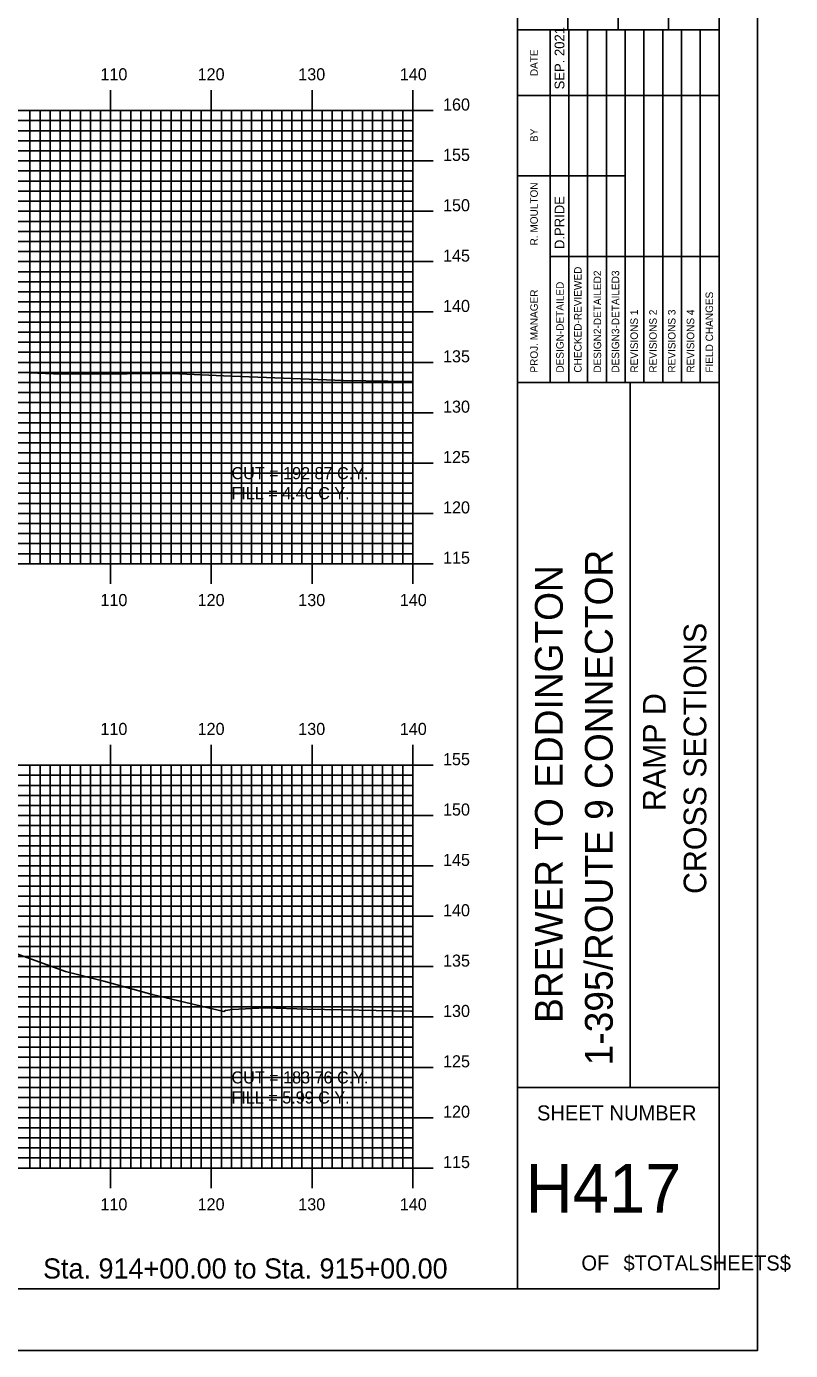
# Model space of a CAD drawing. Extents: x 860652 to 860995, y 364765 to 364985.
# Drawn here: x 860919.1 to 860994.9, y 364765.2 to 364896.6 of the extents above; entities that cross this region are included whole.
import ezdxf

# ---------------------------------------------------------------- set-up
doc = ezdxf.new("R2010")
doc.units = 0
for name, color, linetype in [('BORDER', 7, 'Continuous'), ('D_Text_Standard', 7, 'Continuous'), ('H_V ANNOTATION', 7, 'Continuous'), ('MAJOR', 7, 'Continuous'), ('MINOR', 7, 'Continuous'), ('PLOT BOUNDARY', 7, 'Continuous'), ('S_Roadway_Centerline', 7, 'Continuous')]:
    doc.layers.add(name, color=color, linetype=linetype)

msp = doc.modelspace()

# ---------------------------------------------------------------- linework, layer by layer
at = {"layer": 'BORDER'}
for p, q in [((860967.81, 364771.3), (860967.81, 364981.3)), ((860972.81, 364896.31), (860972.81, 364913.6)), ((860977.81, 364896.31), (860977.81, 364913.6)), ((860982.81, 364896.31), (860982.81, 364913.6)), ((860967.81, 364896.31), (860987.81, 364896.31)), ((860967.81, 364861.31), (860987.81, 364861.31)), ((860978.99, 364791.31), (860978.99, 364861.31)), ((860967.81, 364791.31), (860987.81, 364791.31))]:
    msp.add_line(p, q, dxfattribs=at)
msp.add_lwpolyline([(860667.81, 364771.3), (860987.81, 364771.3), (860987.81, 364981.3), (860667.81, 364981.3)], close=True, dxfattribs=at)
for points in [[(860971.04, 364889.81), (860971.04, 364896.31)], [(860972.91, 364861.31), (860972.91, 364896.31)], [(860974.77, 364896.31), (860974.77, 364861.31)], [(860976.63, 364861.31), (860976.63, 364896.31)], [(860978.5, 364861.31), (860978.5, 364896.31)], [(860980.36, 364861.31), (860980.36, 364896.31)], [(860982.22, 364861.31), (860982.22, 364896.31)], [(860984.09, 364861.31), (860984.09, 364896.31)], [(860985.95, 364861.31), (860985.95, 364896.31)], [(860971.04, 364861.31), (860971.04, 364894.9)], [(860967.81, 364889.81), (860987.81, 364889.81)], [(860967.81, 364881.81), (860971.04, 364881.81)], [(860971.04, 364881.81), (860978.5, 364881.81)], [(860971.04, 364873.81), (860987.81, 364873.81)]]:
    msp.add_lwpolyline(points, dxfattribs=at)
at = {"layer": 'MAJOR'}
for p, q in [((860927.41, 364890.31), (860927.41, 364888.3)), ((860937.41, 364890.31), (860937.41, 364888.3)), ((860947.41, 364890.31), (860947.41, 364888.3)), ((860957.41, 364890.31), (860957.41, 364888.3)), ((860677.41, 364888.3), (860957.41, 364888.3)), ((860677.41, 364888.3), (860957.41, 364888.3)), ((860927.41, 364843.3), (860927.41, 364888.3)), ((860937.41, 364843.3), (860937.41, 364888.3)), ((860947.41, 364843.3), (860947.41, 364888.3)), ((860959.42, 364888.3), (860955.41, 364888.3)), ((860957.41, 364843.3), (860957.41, 364888.3)), ((860957.41, 364843.3), (860957.41, 364888.3)), ((860677.41, 364883.3), (860957.41, 364883.3)), ((860959.42, 364883.3), (860955.41, 364883.3)), ((860677.41, 364878.3), (860957.41, 364878.3)), ((860959.42, 364878.3), (860955.41, 364878.3)), ((860677.41, 364873.3), (860957.41, 364873.3)), ((860959.42, 364873.3), (860955.41, 364873.3)), ((860677.41, 364868.3), (860957.41, 364868.3)), ((860959.42, 364868.3), (860955.41, 364868.3)), ((860677.41, 364863.3), (860957.41, 364863.3)), ((860959.42, 364863.3), (860955.41, 364863.3)), ((860677.41, 364858.3), (860957.41, 364858.3)), ((860959.42, 364858.3), (860955.41, 364858.3)), ((860677.41, 364853.3), (860957.41, 364853.3)), ((860959.42, 364853.3), (860955.41, 364853.3)), ((860677.41, 364848.3), (860957.41, 364848.3)), ((860959.42, 364848.3), (860955.41, 364848.3)), ((860677.41, 364843.3), (860957.41, 364843.3)), ((860677.41, 364843.3), (860957.41, 364843.3)), ((860927.41, 364841.3), (860927.41, 364843.3)), ((860937.41, 364841.3), (860937.41, 364843.3)), ((860947.41, 364841.3), (860947.41, 364843.3)), ((860959.42, 364843.3), (860955.41, 364843.3)), ((860957.41, 364841.3), (860957.41, 364843.3)), ((860927.41, 364825.31), (860927.41, 364823.3)), ((860937.41, 364825.31), (860937.41, 364823.3)), ((860947.41, 364825.31), (860947.41, 364823.3)), ((860957.41, 364825.31), (860957.41, 364823.3)), ((860677.41, 364823.3), (860957.41, 364823.3)), ((860677.41, 364823.3), (860957.41, 364823.3)), ((860927.41, 364783.3), (860927.41, 364823.3)), ((860937.41, 364783.3), (860937.41, 364823.3)), ((860947.41, 364783.3), (860947.41, 364823.3)), ((860959.42, 364823.3), (860955.41, 364823.3)), ((860957.41, 364783.3), (860957.41, 364823.3)), ((860957.41, 364783.3), (860957.41, 364823.3)), ((860677.41, 364818.3), (860957.41, 364818.3)), ((860959.42, 364818.3), (860955.41, 364818.3)), ((860677.41, 364813.3), (860957.41, 364813.3)), ((860959.42, 364813.3), (860955.41, 364813.3)), ((860677.41, 364808.3), (860957.41, 364808.3)), ((860959.42, 364808.3), (860955.41, 364808.3)), ((860677.41, 364803.3), (860957.41, 364803.3)), ((860959.42, 364803.3), (860955.41, 364803.3)), ((860677.41, 364798.3), (860957.41, 364798.3)), ((860959.42, 364798.3), (860955.41, 364798.3)), ((860677.41, 364793.3), (860957.41, 364793.3)), ((860959.42, 364793.3), (860955.41, 364793.3)), ((860677.41, 364788.3), (860957.41, 364788.3)), ((860959.42, 364788.3), (860955.41, 364788.3)), ((860677.41, 364783.3), (860957.41, 364783.3)), ((860677.41, 364783.3), (860957.41, 364783.3)), ((860927.41, 364781.3), (860927.41, 364783.3)), ((860937.41, 364781.3), (860937.41, 364783.3)), ((860947.41, 364781.3), (860947.41, 364783.3)), ((860959.42, 364783.3), (860955.41, 364783.3)), ((860957.41, 364781.3), (860957.41, 364783.3))]:
    msp.add_line(p, q, dxfattribs=at)
at = {"layer": 'MINOR'}
for p, q in [((860919.41, 364843.3), (860919.41, 364888.3)), ((860920.41, 364843.3), (860920.41, 364888.3)), ((860921.41, 364843.3), (860921.41, 364888.3)), ((860922.41, 364843.3), (860922.41, 364888.3)), ((860923.41, 364843.3), (860923.41, 364888.3)), ((860924.41, 364843.3), (860924.41, 364888.3)), ((860925.41, 364843.3), (860925.41, 364888.3)), ((860926.41, 364843.3), (860926.41, 364888.3)), ((860928.41, 364843.3), (860928.41, 364888.3)), ((860929.41, 364843.3), (860929.41, 364888.3)), ((860930.41, 364843.3), (860930.41, 364888.3)), ((860931.41, 364843.3), (860931.41, 364888.3)), ((860932.41, 364843.3), (860932.41, 364888.3)), ((860933.41, 364843.3), (860933.41, 364888.3)), ((860934.41, 364843.3), (860934.41, 364888.3)), ((860935.41, 364843.3), (860935.41, 364888.3)), ((860936.41, 364843.3), (860936.41, 364888.3)), ((860938.41, 364843.3), (860938.41, 364888.3)), ((860939.41, 364843.3), (860939.41, 364888.3)), ((860940.41, 364843.3), (860940.41, 364888.3)), ((860941.41, 364843.3), (860941.41, 364888.3)), ((860942.41, 364843.3), (860942.41, 364888.3)), ((860943.41, 364843.3), (860943.41, 364888.3)), ((860944.41, 364843.3), (860944.41, 364888.3)), ((860945.41, 364843.3), (860945.41, 364888.3)), ((860946.41, 364843.3), (860946.41, 364888.3)), ((860948.41, 364843.3), (860948.41, 364888.3)), ((860949.41, 364843.3), (860949.41, 364888.3)), ((860950.41, 364843.3), (860950.41, 364888.3)), ((860951.41, 364843.3), (860951.41, 364888.3)), ((860952.41, 364843.3), (860952.41, 364888.3)), ((860953.41, 364843.3), (860953.41, 364888.3)), ((860954.41, 364843.3), (860954.41, 364888.3)), ((860955.41, 364843.3), (860955.41, 364888.3)), ((860956.41, 364843.3), (860956.41, 364888.3)), ((860677.41, 364887.3), (860957.41, 364887.3)), ((860957.41, 364887.3), (860955.41, 364887.3)), ((860677.41, 364886.3), (860957.41, 364886.3)), ((860677.41, 364885.3), (860957.41, 364885.3)), ((860957.41, 364886.3), (860955.41, 364886.3)), ((860957.41, 364885.3), (860955.41, 364885.3)), ((860677.41, 364884.3), (860957.41, 364884.3)), ((860957.41, 364884.3), (860955.41, 364884.3)), ((860677.41, 364882.3), (860957.41, 364882.3)), ((860957.41, 364882.3), (860955.41, 364882.3)), ((860677.41, 364881.3), (860957.41, 364881.3)), ((860677.41, 364880.3), (860957.41, 364880.3)), ((860957.41, 364881.3), (860955.41, 364881.3)), ((860957.41, 364880.3), (860955.41, 364880.3)), ((860677.41, 364879.3), (860957.41, 364879.3)), ((860957.41, 364879.3), (860955.41, 364879.3)), ((860677.41, 364877.3), (860957.41, 364877.3)), ((860677.41, 364876.3), (860957.41, 364876.3)), ((860957.41, 364877.3), (860955.41, 364877.3)), ((860957.41, 364876.3), (860955.41, 364876.3)), ((860677.41, 364875.3), (860957.41, 364875.3)), ((860957.41, 364875.3), (860955.41, 364875.3)), ((860677.41, 364874.3), (860957.41, 364874.3)), ((860957.41, 364874.3), (860955.41, 364874.3)), ((860677.41, 364872.3), (860957.41, 364872.3)), ((860957.41, 364872.3), (860955.41, 364872.3)), ((860677.41, 364871.3), (860957.41, 364871.3)), ((860957.41, 364871.3), (860955.41, 364871.3)), ((860677.41, 364870.3), (860957.41, 364870.3)), ((860957.41, 364870.3), (860955.41, 364870.3)), ((860677.41, 364869.3), (860957.41, 364869.3)), ((860957.41, 364869.3), (860955.41, 364869.3)), ((860677.41, 364867.3), (860957.41, 364867.3)), ((860957.41, 364867.3), (860955.41, 364867.3)), ((860677.41, 364866.3), (860957.41, 364866.3)), ((860957.41, 364866.3), (860955.41, 364866.3)), ((860677.41, 364865.3), (860957.41, 364865.3)), ((860677.41, 364864.3), (860957.41, 364864.3)), ((860957.41, 364865.3), (860955.41, 364865.3)), ((860957.41, 364864.3), (860955.41, 364864.3)), ((860677.41, 364862.3), (860957.41, 364862.3)), ((860957.41, 364862.3), (860955.41, 364862.3)), ((860677.41, 364861.3), (860957.41, 364861.3)), ((860677.41, 364860.3), (860957.41, 364860.3)), ((860957.41, 364861.3), (860955.41, 364861.3)), ((860957.41, 364860.3), (860955.41, 364860.3)), ((860677.41, 364859.3), (860957.41, 364859.3)), ((860957.41, 364859.3), (860955.41, 364859.3)), ((860677.41, 364857.3), (860957.41, 364857.3)), ((860957.41, 364857.3), (860955.41, 364857.3)), ((860677.41, 364856.3), (860957.41, 364856.3)), ((860677.41, 364855.3), (860957.41, 364855.3)), ((860957.41, 364856.3), (860955.41, 364856.3)), ((860957.41, 364855.3), (860955.41, 364855.3)), ((860677.41, 364854.3), (860957.41, 364854.3)), ((860957.41, 364854.3), (860955.41, 364854.3)), ((860677.41, 364852.3), (860957.41, 364852.3)), ((860677.41, 364851.3), (860957.41, 364851.3)), ((860957.41, 364852.3), (860955.41, 364852.3)), ((860957.41, 364851.3), (860955.41, 364851.3)), ((860677.41, 364850.3), (860957.41, 364850.3)), ((860957.41, 364850.3), (860955.41, 364850.3)), ((860677.41, 364849.3), (860957.41, 364849.3)), ((860957.41, 364849.3), (860955.41, 364849.3)), ((860677.41, 364847.3), (860957.41, 364847.3)), ((860957.41, 364847.3), (860955.41, 364847.3)), ((860677.41, 364846.3), (860957.41, 364846.3)), ((860957.41, 364846.3), (860955.41, 364846.3)), ((860677.41, 364845.3), (860957.41, 364845.3)), ((860957.41, 364845.3), (860955.41, 364845.3)), ((860677.41, 364844.3), (860957.41, 364844.3)), ((860957.41, 364844.3), (860955.41, 364844.3)), ((860677.41, 364822.3), (860957.41, 364822.3)), ((860919.41, 364783.3), (860919.41, 364823.3)), ((860920.41, 364783.3), (860920.41, 364823.3)), ((860921.41, 364783.3), (860921.41, 364823.3)), ((860922.41, 364783.3), (860922.41, 364823.3)), ((860923.41, 364783.3), (860923.41, 364823.3)), ((860924.41, 364783.3), (860924.41, 364823.3)), ((860925.41, 364783.3), (860925.41, 364823.3)), ((860926.41, 364783.3), (860926.41, 364823.3)), ((860928.41, 364783.3), (860928.41, 364823.3)), ((860929.41, 364783.3), (860929.41, 364823.3)), ((860930.41, 364783.3), (860930.41, 364823.3)), ((860931.41, 364783.3), (860931.41, 364823.3)), ((860932.41, 364783.3), (860932.41, 364823.3)), ((860933.41, 364783.3), (860933.41, 364823.3)), ((860934.41, 364783.3), (860934.41, 364823.3)), ((860935.41, 364783.3), (860935.41, 364823.3)), ((860936.41, 364783.3), (860936.41, 364823.3)), ((860938.41, 364783.3), (860938.41, 364823.3)), ((860939.41, 364783.3), (860939.41, 364823.3)), ((860940.41, 364783.3), (860940.41, 364823.3)), ((860941.41, 364783.3), (860941.41, 364823.3)), ((860942.41, 364783.3), (860942.41, 364823.3)), ((860943.41, 364783.3), (860943.41, 364823.3)), ((860944.41, 364783.3), (860944.41, 364823.3)), ((860945.41, 364783.3), (860945.41, 364823.3)), ((860946.41, 364783.3), (860946.41, 364823.3)), ((860948.41, 364783.3), (860948.41, 364823.3)), ((860949.41, 364783.3), (860949.41, 364823.3)), ((860950.41, 364783.3), (860950.41, 364823.3)), ((860951.41, 364783.3), (860951.41, 364823.3)), ((860952.41, 364783.3), (860952.41, 364823.3)), ((860953.41, 364783.3), (860953.41, 364823.3)), ((860954.41, 364783.3), (860954.41, 364823.3)), ((860955.41, 364783.3), (860955.41, 364823.3)), ((860957.41, 364822.3), (860955.41, 364822.3)), ((860956.41, 364783.3), (860956.41, 364823.3)), ((860677.41, 364821.3), (860957.41, 364821.3)), ((860957.41, 364821.3), (860955.41, 364821.3)), ((860677.41, 364820.3), (860957.41, 364820.3)), ((860957.41, 364820.3), (860955.41, 364820.3)), ((860677.41, 364819.3), (860957.41, 364819.3)), ((860957.41, 364819.3), (860955.41, 364819.3)), ((860677.41, 364817.3), (860957.41, 364817.3)), ((860957.41, 364817.3), (860955.41, 364817.3)), ((860677.41, 364816.3), (860957.41, 364816.3)), ((860957.41, 364816.3), (860955.41, 364816.3)), ((860677.41, 364815.3), (860957.41, 364815.3)), ((860677.41, 364814.3), (860957.41, 364814.3)), ((860957.41, 364815.3), (860955.41, 364815.3)), ((860957.41, 364814.3), (860955.41, 364814.3)), ((860677.41, 364812.3), (860957.41, 364812.3)), ((860957.41, 364812.3), (860955.41, 364812.3)), ((860677.41, 364811.3), (860957.41, 364811.3)), ((860957.41, 364811.3), (860955.41, 364811.3)), ((860677.41, 364810.3), (860957.41, 364810.3)), ((860677.41, 364809.3), (860957.41, 364809.3)), ((860957.41, 364810.3), (860955.41, 364810.3)), ((860957.41, 364809.3), (860955.41, 364809.3)), ((860677.41, 364807.3), (860957.41, 364807.3)), ((860957.41, 364807.3), (860955.41, 364807.3)), ((860677.41, 364806.3), (860957.41, 364806.3)), ((860677.41, 364805.3), (860957.41, 364805.3)), ((860957.41, 364806.3), (860955.41, 364806.3)), ((860957.41, 364805.3), (860955.41, 364805.3)), ((860677.41, 364804.3), (860957.41, 364804.3)), ((860957.41, 364804.3), (860955.41, 364804.3)), ((860677.41, 364802.3), (860957.41, 364802.3)), ((860677.41, 364801.3), (860957.41, 364801.3)), ((860957.41, 364802.3), (860955.41, 364802.3)), ((860957.41, 364801.3), (860955.41, 364801.3)), ((860677.41, 364800.3), (860957.41, 364800.3)), ((860957.41, 364800.3), (860955.41, 364800.3)), ((860677.41, 364799.3), (860957.41, 364799.3)), ((860957.41, 364799.3), (860955.41, 364799.3)), ((860677.41, 364797.3), (860957.41, 364797.3)), ((860957.41, 364797.3), (860955.41, 364797.3)), ((860677.41, 364796.3), (860957.41, 364796.3)), ((860957.41, 364796.3), (860955.41, 364796.3)), ((860677.41, 364795.3), (860957.41, 364795.3)), ((860957.41, 364795.3), (860955.41, 364795.3)), ((860677.41, 364794.3), (860957.41, 364794.3)), ((860957.41, 364794.3), (860955.41, 364794.3)), ((860677.41, 364792.3), (860957.41, 364792.3)), ((860957.41, 364792.3), (860955.41, 364792.3)), ((860677.41, 364791.3), (860957.41, 364791.3)), ((860957.41, 364791.3), (860955.41, 364791.3)), ((860677.41, 364790.3), (860957.41, 364790.3)), ((860957.41, 364790.3), (860955.41, 364790.3)), ((860677.41, 364789.3), (860957.41, 364789.3)), ((860957.41, 364789.3), (860955.41, 364789.3)), ((860677.41, 364787.3), (860957.41, 364787.3)), ((860957.41, 364787.3), (860955.41, 364787.3)), ((860677.41, 364786.3), (860957.41, 364786.3)), ((860957.41, 364786.3), (860955.41, 364786.3)), ((860677.41, 364785.3), (860957.41, 364785.3)), ((860677.41, 364784.3), (860957.41, 364784.3)), ((860957.41, 364785.3), (860955.41, 364785.3)), ((860957.41, 364784.3), (860955.41, 364784.3))]:
    msp.add_line(p, q, dxfattribs=at)
at = {"layer": 'PLOT BOUNDARY'}
msp.add_lwpolyline([(860651.63, 364765.18), (860991.63, 364765.18), (860991.63, 364985.18), (860651.63, 364985.18)], close=True, dxfattribs=at)
at = {"layer": 'S_Roadway_Centerline'}
for points in [[(860834.52, 364875.53), (860843.92, 364872.7), (860849.87, 364871.04), (860850.13, 364871.01), (860858.57, 364872.87), (860866.42, 364873.62), (860875.94, 364873.76), (860888.54, 364869.71), (860888.59, 364869.7), (860888.77, 364869.62), (860906.84, 364861.8), (860909.88, 364862.09), (860911.39, 364862.31), (860912.25, 364862.59), (860915.45, 364862.44), (860921.73, 364862.17), (860929.07, 364862.17), (860933.52, 364862.19), (860938.62, 364861.95), (860950.53, 364861.49), (860957.15, 364861.41), (860957.41, 364861.4)], [(860841.48, 364809.12), (860849.63, 364806.32), (860859.81, 364803.67), (860863.22, 364804.79), (860866.95, 364805.6), (860879.47, 364807.84), (860885.13, 364807.42), (860902.91, 364809.9), (860905.02, 364809.12), (860911.67, 364806.89), (860922.92, 364802.81), (860926.73, 364801.86), (860931.55, 364800.54), (860938.64, 364798.85), (860938.83, 364798.96), (860939.47, 364799.06), (860942.79, 364799.2), (860946.92, 364799.09), (860957.22, 364798.89), (860957.41, 364798.89)]]:
    msp.add_lwpolyline(points, dxfattribs=at)

# ---------------------------------------------------------------- texts
at = {"layer": 'BORDER'}
for s, height, p in [('SEP. 2021', 0.969, (860972.46, 364890.4)), ('DATE', 0.743, (860969.82, 364891.72)), ('BY', 0.743, (860969.82, 364885.18)), ('R. MOULTON', 0.745, (860969.82, 364874.91)), ('D.PRIDE', 0.969, (860972.46, 364874.55)), ('CHECKED-REVIEWED', 0.7455, (860974.17, 364862.28)), ('DESIGN2-DETAILED2', 0.7455, (860976.11, 364862.28)), ('DESIGN3-DETAILED3', 0.7455, (860977.9, 364862.28)), ('DESIGN-DETAILED', 0.7455, (860972.39, 364862.28)), ('PROJ. MANAGER', 0.7455, (860969.82, 364862.28)), ('FIELD CHANGES', 0.7455, (860987.22, 364862.28)), ('REVISIONS 1', 0.7455, (860979.76, 364862.28)), ('REVISIONS 2', 0.7455, (860981.63, 364862.28)), ('REVISIONS 3', 0.7455, (860983.49, 364862.28)), ('REVISIONS 4', 0.7455, (860985.35, 364862.28)), ('1-395/ROUTE 9 CONNECTOR', 2.7557, (860977.26, 364793.5)), ('BREWER TO EDDINGTON', 2.7557, (860972.3, 364797.71)), ('CROSS SECTIONS', 2.25, (860986.55, 364810.52)), ('RAMP D', 2.25, (860982.5, 364818.75))]:
    msp.add_text(s, height=height, rotation=90, dxfattribs=at).set_placement(p)
for s, height, p in [('SHEET NUMBER', 1.4905, (860969.74, 364788.03)), ('H417', 4.839, (860968.61, 364778.87)), ('OF', 1.491, (860974.15, 364773.13)), ('$TOTALSHEETS$', 1.4905, (860978.33, 364773.13))]:
    msp.add_text(s, height=height, dxfattribs=at).set_placement(p)
at = {"layer": 'D_Text_Standard'}
for s, p in [('CUT = 192.87 C.Y.', (860939.41, 364851.7)), ('FILL = 4.40 C.Y.', (860939.41, 364849.71)), ('CUT = 183.76 C.Y.', (860939.41, 364791.7)), ('FILL = 5.99 C.Y.', (860939.41, 364789.71))]:
    msp.add_text(s, height=1.2, dxfattribs=at).set_placement(p)
at = {"layer": 'H_V ANNOTATION'}
for s, height, p in [('110', 1.2, (860926.4, 364891.3)), ('120', 1.2, (860936.05, 364891.3)), ('130', 1.2, (860946.04, 364891.3)), ('140', 1.2, (860956.12, 364891.3)), ('160', 1.2, (860960.41, 364888.3)), ('155', 1.2, (860960.41, 364883.3)), ('150', 1.2, (860960.41, 364878.3)), ('145', 1.2, (860960.41, 364873.3)), ('140', 1.2, (860960.41, 364868.3)), ('135', 1.2, (860960.41, 364863.3)), ('130', 1.2, (860960.41, 364858.3)), ('125', 1.2, (860960.41, 364853.3)), ('120', 1.2, (860960.41, 364848.3)), ('115', 1.2, (860960.41, 364843.3)), ('110', 1.2, (860926.4, 364839.1)), ('120', 1.2, (860936.05, 364839.1)), ('130', 1.2, (860946.04, 364839.1)), ('140', 1.2, (860956.12, 364839.1)), ('110', 1.2, (860926.4, 364826.3)), ('120', 1.2, (860936.05, 364826.3)), ('130', 1.2, (860946.04, 364826.3)), ('140', 1.2, (860956.12, 364826.3)), ('155', 1.2, (860960.41, 364823.3)), ('150', 1.2, (860960.41, 364818.3)), ('145', 1.2, (860960.41, 364813.3)), ('140', 1.2, (860960.41, 364808.3)), ('135', 1.2, (860960.41, 364803.3)), ('130', 1.2, (860960.41, 364798.3)), ('125', 1.2, (860960.41, 364793.3)), ('120', 1.2, (860960.41, 364788.3)), ('115', 1.2, (860960.41, 364783.3)), ('110', 1.2, (860926.4, 364779.1)), ('120', 1.2, (860936.05, 364779.1)), ('130', 1.2, (860946.04, 364779.1)), ('140', 1.2, (860956.12, 364779.1)), ('Sta. 914+00.00 to Sta. 915+00.00', 2.0004, (860920.71, 364772.33))]:
    msp.add_text(s, height=height, dxfattribs=at).set_placement(p)

doc.saveas('drawing.dxf')
